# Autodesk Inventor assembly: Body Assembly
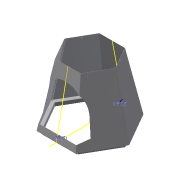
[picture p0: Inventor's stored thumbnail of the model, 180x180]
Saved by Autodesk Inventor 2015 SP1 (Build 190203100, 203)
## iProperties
Created: 2013-06
Part Number: Body Assembly
Document SubType Name: Assembly
Designer: BarryWSUK
Author: BarryWSUK
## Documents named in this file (3)
- \\psf\Home\Documents\Inventor\Sau Paulo Chimnea\Body Assembly.iam
- \\psf\Home\Documents\Inventor\Sau Paulo Chimnea\Body Part A.ipt
- \\psf\Home\Documents\Inventor\Sau Paulo Chimnea\Body Part B.ipt
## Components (2 placed, 2 different names)
1. Body Part A:1 — Mate:1, Mate:2, Flush:1
2. Body Part B:1 — Mate:1, Mate:2, Flush:1
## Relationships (3: Mate 2, Flush 1)
- Mate:1: Body Part A:1 ↔ Body Part B:1
- Mate:2: Body Part A:1 ↔ Body Part B:1
- Flush:1: Body Part A:1 ↔ Body Part B:1
